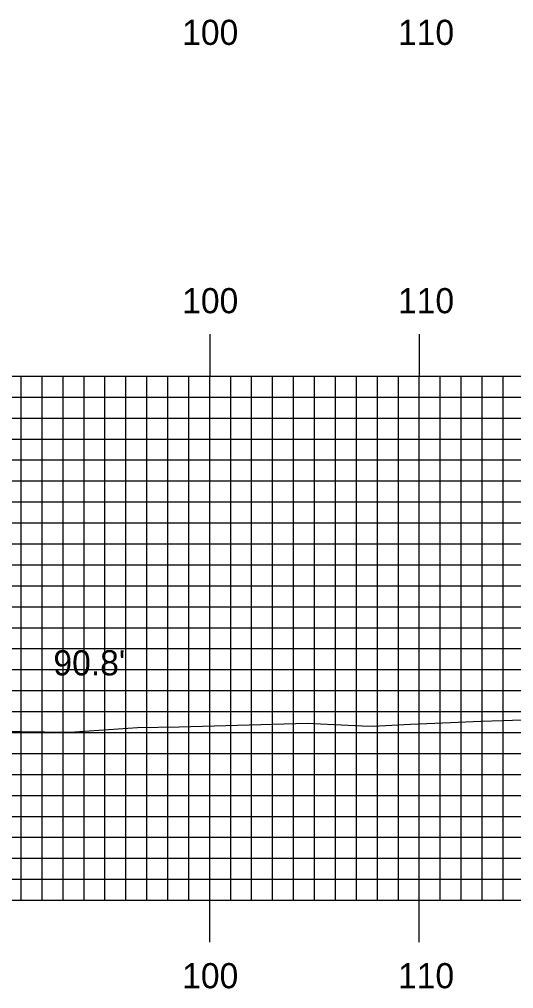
# Model space of a CAD drawing. Extents: x 1763365 to 1763708, y 442591 to 442811.
# Drawn here: x 1763621.72 to 1763645.31, y 442709.45 to 442755.68 of the extents above; entities that cross this region are included whole.
import ezdxf

# ---------------------------------------------------------------- set-up
doc = ezdxf.new("R2010")
doc.units = 0
for name, color, linetype in [('D_Text_Standard', 7, 'Continuous'), ('H_V ANNOTATION', 7, 'Continuous'), ('MAJOR', 7, 'Continuous'), ('MINOR', 7, 'Continuous'), ('S_Roadway_Centerline', 7, 'Continuous')]:
    doc.layers.add(name, color=color, linetype=linetype)

msp = doc.modelspace()

# ---------------------------------------------------------------- linework, layer by layer
at = {"layer": 'MAJOR'}
for p, q in [((1763630.805, 442740.669), (1763630.805, 442738.665)), ((1763640.805, 442740.669), (1763640.805, 442738.665)), ((1763390.805, 442738.665), (1763670.805, 442738.665)), ((1763390.805, 442738.665), (1763670.805, 442738.665)), ((1763630.805, 442713.665), (1763630.805, 442738.665)), ((1763640.805, 442713.665), (1763640.805, 442738.665)), ((1763390.805, 442733.665), (1763670.805, 442733.665)), ((1763390.805, 442728.665), (1763670.805, 442728.665)), ((1763390.805, 442723.665), (1763670.805, 442723.665)), ((1763390.805, 442718.665), (1763670.805, 442718.665)), ((1763390.805, 442713.665), (1763670.805, 442713.665)), ((1763390.805, 442713.665), (1763670.805, 442713.665)), ((1763630.805, 442711.661), (1763630.805, 442713.665)), ((1763640.805, 442711.661), (1763640.805, 442713.665))]:
    msp.add_line(p, q, dxfattribs=at)
at = {"layer": 'MINOR'}
for p, q in [((1763621.805, 442713.665), (1763621.805, 442738.665)), ((1763622.805, 442713.665), (1763622.805, 442738.665)), ((1763623.805, 442713.665), (1763623.805, 442738.665)), ((1763624.805, 442713.665), (1763624.805, 442738.665)), ((1763625.805, 442713.665), (1763625.805, 442738.665)), ((1763626.805, 442713.665), (1763626.805, 442738.665)), ((1763627.805, 442713.665), (1763627.805, 442738.665)), ((1763628.805, 442713.665), (1763628.805, 442738.665)), ((1763629.805, 442713.665), (1763629.805, 442738.665)), ((1763631.805, 442713.665), (1763631.805, 442738.665)), ((1763632.805, 442713.665), (1763632.805, 442738.665)), ((1763633.805, 442713.665), (1763633.805, 442738.665)), ((1763634.805, 442713.665), (1763634.805, 442738.665)), ((1763635.805, 442713.665), (1763635.805, 442738.665)), ((1763636.805, 442713.665), (1763636.805, 442738.665)), ((1763637.805, 442713.665), (1763637.805, 442738.665)), ((1763638.805, 442713.665), (1763638.805, 442738.665)), ((1763639.805, 442713.665), (1763639.805, 442738.665)), ((1763641.805, 442713.665), (1763641.805, 442738.665)), ((1763642.805, 442713.665), (1763642.805, 442738.665)), ((1763643.805, 442713.665), (1763643.805, 442738.665)), ((1763644.805, 442713.665), (1763644.805, 442738.665)), ((1763390.805, 442737.665), (1763670.805, 442737.665)), ((1763390.805, 442736.665), (1763670.805, 442736.665)), ((1763390.805, 442735.665), (1763670.805, 442735.665)), ((1763390.805, 442734.665), (1763670.805, 442734.665)), ((1763390.805, 442732.665), (1763670.805, 442732.665)), ((1763390.805, 442731.665), (1763670.805, 442731.665)), ((1763390.805, 442730.665), (1763670.805, 442730.665)), ((1763390.805, 442729.665), (1763670.805, 442729.665)), ((1763390.805, 442727.665), (1763670.805, 442727.665)), ((1763390.805, 442726.665), (1763670.805, 442726.665)), ((1763390.805, 442725.665), (1763670.805, 442725.665)), ((1763390.805, 442724.665), (1763670.805, 442724.665)), ((1763390.805, 442722.665), (1763670.805, 442722.665)), ((1763390.805, 442721.665), (1763670.805, 442721.665)), ((1763390.805, 442720.665), (1763670.805, 442720.665)), ((1763390.805, 442720.665), (1763670.805, 442720.665)), ((1763390.805, 442719.665), (1763670.805, 442719.665)), ((1763390.805, 442717.665), (1763670.805, 442717.665)), ((1763390.805, 442716.665), (1763670.805, 442716.665)), ((1763390.805, 442715.665), (1763670.805, 442715.665)), ((1763390.805, 442714.665), (1763670.805, 442714.665))]:
    msp.add_line(p, q, dxfattribs=at)
at = {"layer": 'S_Roadway_Centerline'}
msp.add_lwpolyline([(1763616.98, 442721.77), (1763624.132, 442721.681), (1763627.355, 442721.903), (1763629.342, 442721.941), (1763635.464, 442722.115), (1763636.086, 442722.081), (1763636.737, 442722.047), (1763637.407, 442722.015), (1763638.078, 442721.988), (1763638.608, 442721.97), (1763639.198, 442722.002), (1763640.378, 442722.059), (1763641.538, 442722.111), (1763642.663, 442722.158), (1763643.743, 442722.2), (1763644.767, 442722.237), (1763645.728, 442722.271)], dxfattribs=at)

# ---------------------------------------------------------------- texts
at = {"layer": 'D_Text_Standard'}
msp.add_text("90.8'", height=1.2, dxfattribs=at).set_placement((1763623.344, 442724.391))
at = {"layer": 'H_V ANNOTATION'}
for s, p in [('100', (1763629.489, 442754.465)), ('110', (1763639.789, 442754.465)), ('100', (1763629.489, 442741.665)), ('110', (1763639.789, 442741.665)), ('100', (1763629.489, 442709.465)), ('110', (1763639.789, 442709.465))]:
    msp.add_text(s, height=1.2, dxfattribs=at).set_placement(p)

doc.saveas('drawing.dxf')
